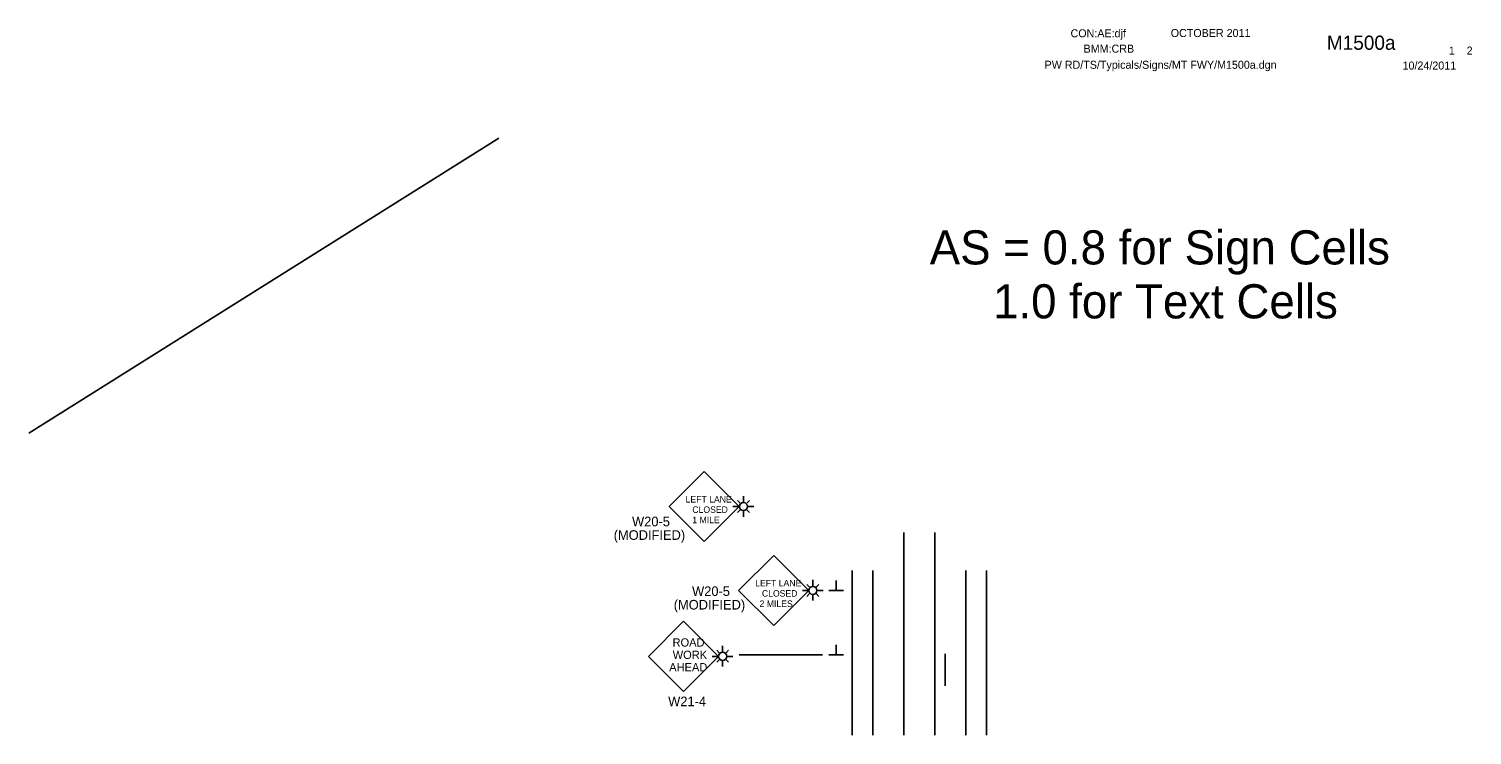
# Model space of a CAD drawing. Extents: x 16284 to 18474, y 5417 to 6974.
# Drawn here: x 16284 to 17402, y 5417 to 5965 of the extents above; entities that cross this region are included whole.
import ezdxf

# ---------------------------------------------------------------- set-up
doc = ezdxf.new("R2010")
doc.units = 0
for name, color, linetype in [('ALI_LEGAL_EX', 7, 'Continuous'), ('BORDER_SIGNAL_WO', 7, 'Continuous'), ('PAVT_EDGE_EX', 7, 'Continuous'), ('TRAFFIC_SIGNS_PR', 7, 'Continuous'), ('TYPICAL_TEXT_DIMEN_PR', 7, 'Continuous')]:
    doc.layers.add(name, color=color, linetype=linetype)

msp = doc.modelspace()

# ---------------------------------------------------------------- linework, layer by layer
at = {"layer": 'ALI_LEGAL_EX'}
for p, q in [((16961.5, 5574.3), (16961.5, 5417.4)), ((16985.5, 5574.3), (16985.5, 5417.4))]:
    msp.add_line(p, q, dxfattribs=at)
for points in [[(16961.5, 5544.9), (16961.5, 5519.9)], [(16985.5, 5544.9), (16985.5, 5519.9)], [(16993.6, 5480.5), (16993.6, 5455.5)], [(16961.5, 5444.9), (16961.5, 5419.9)], [(16985.5, 5444.9), (16985.5, 5419.9)]]:
    msp.add_lwpolyline(points, dxfattribs=at)
at = {"layer": 'PAVT_EDGE_EX'}
for p, q in [((16921.5, 5544.9), (16921.5, 5417.4)), ((16937.5, 5544.9), (16937.5, 5417.4)), ((17009.5, 5544.9), (17009.5, 5417.4)), ((17025.5, 5544.9), (17025.5, 5417.4))]:
    msp.add_line(p, q, dxfattribs=at)
at = {"layer": 'TRAFFIC_SIGNS_PR'}
for p, q in [((16806.9, 5621.7), (16779.7, 5594.5)), ((16834.1, 5594.5), (16806.9, 5621.7)), ((16837.3, 5598), (16837.3, 5602.5)), ((16779.7, 5594.5), (16806.9, 5567.3)), ((16806.9, 5567.3), (16834.1, 5594.5)), ((16834.1, 5594.5), (16829.2, 5594.5)), ((16834.8, 5597), (16832.6, 5599.1)), ((16834.8, 5592), (16832.6, 5589.9)), ((16837.3, 5586.5), (16837.3, 5590.9)), ((16839.8, 5597), (16841.9, 5599.1)), ((16839.8, 5592), (16841.9, 5589.9)), ((16840.4, 5594.5), (16845.3, 5594.5)), ((16860.8, 5556.7), (16833.6, 5529.5)), ((16887.9, 5529.5), (16860.8, 5556.7)), ((16888.6, 5532), (16886.5, 5534.1)), ((16891.1, 5533.1), (16891.1, 5537.6)), ((16893.6, 5532), (16895.7, 5534.1)), ((16833.6, 5529.5), (16860.8, 5502.3)), ((16860.8, 5502.3), (16887.9, 5529.5)), ((16887.9, 5529.5), (16883.1, 5529.5)), ((16888.6, 5527), (16886.5, 5524.9)), ((16891.1, 5521.6), (16891.1, 5526)), ((16893.6, 5527), (16895.7, 5524.9)), ((16894.2, 5529.5), (16899.1, 5529.5)), ((16790.8, 5505.6), (16763.7, 5478.4)), ((16818, 5478.4), (16790.8, 5505.6)), ((16763.7, 5478.4), (16790.8, 5451.3)), ((16790.8, 5451.3), (16818, 5478.4)), ((16818, 5478.4), (16813.1, 5478.4)), ((16818.7, 5481), (16816.6, 5483.1)), ((16821.2, 5482), (16821.2, 5486.5)), ((16823.7, 5481), (16825.8, 5483.1)), ((16824.3, 5478.4), (16829.2, 5478.4)), ((16818.7, 5475.9), (16816.6, 5473.8)), ((16821.2, 5470.5), (16821.2, 5474.9)), ((16823.7, 5475.9), (16825.8, 5473.8))]:
    msp.add_line(p, q, dxfattribs=at)
for centre in [(16837.3, 5594.5), (16891.1, 5529.5), (16821.2, 5478.4)]:
    msp.add_circle(centre, 3.15, dxfattribs=at)
at = {"layer": 'TYPICAL_TEXT_DIMEN_PR'}
for p, q in [((16647.8, 5880), (16283.8, 5651.4)), ((16909.1, 5529.5), (16909.1, 5537.3)), ((16903.5, 5529.5), (16914.8, 5529.5)), ((16834.1, 5479.5), (16898.5, 5479.5)), ((16903.5, 5479.5), (16914.8, 5479.5)), ((16909.1, 5479.5), (16909.1, 5487.3))]:
    msp.add_line(p, q, dxfattribs=at)

# ---------------------------------------------------------------- texts
at = {"layer": 'BORDER_SIGNAL_WO'}
for s, height, p in [('CON:AE:djf  ', 6.2, (17090.7, 5958.1)), ('    OCTOBER 2011    ', 6.2, (17159.1, 5958.3)), ('    M1500a   ', 11, (17272.9, 5948.4)), ('BMM:CRB   ', 6.2, (17100.8, 5946.2)), (' 1    2 ', 6.2, (17381.4, 5944.7)), ('PW RD/TS/Typicals/Signs/MT FWY/M1500a.dgn      ', 6.2, (17070.6, 5933.7)), ('10/24/2011    ', 6.2, (17347.9, 5933.1)), ('AS = 0.8 for Sign Cells', 26.424, (16981.6, 5782.1)), ('     1.0 for Text Cells', 26.424, (16981.6, 5740.3))]:
    msp.add_text(s, height=height, dxfattribs=at).set_placement(p)
at = {"layer": 'TRAFFIC_SIGNS_PR'}
for s, height, p in [('LEFT LANE', 5.01, (16792.5, 5597.6)), ('CLOSED', 5.01, (16797.7, 5589.6)), ('W20-5', 7.45, (16751, 5579.2)), ('1 MILE', 5.01, (16797.7, 5581.6)), ('(MODIFIED)', 7.45, (16736.8, 5568.7)), ('LEFT LANE', 5.01, (16846.4, 5532.7)), ('W20-5', 7.45, (16797.5, 5525.2)), ('CLOSED', 5.01, (16851.6, 5524.7)), ('(MODIFIED)', 7.45, (16783.3, 5514.7)), ('2 MILES', 5.01, (16849.8, 5516.7)), ('ROAD', 6.41, (16782.4, 5486)), ('WORK', 6.41, (16782.5, 5476.4)), ('AHEAD', 6.41, (16779.8, 5466.8)), ('W21-4', 7.45, (16779, 5439.8))]:
    msp.add_text(s, height=height, dxfattribs=at).set_placement(p)

doc.saveas('drawing.dxf')
